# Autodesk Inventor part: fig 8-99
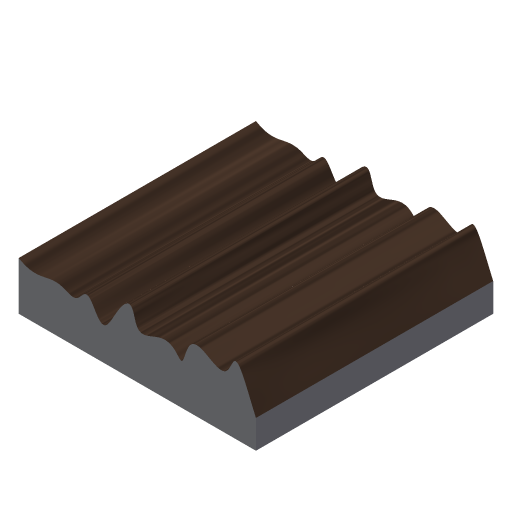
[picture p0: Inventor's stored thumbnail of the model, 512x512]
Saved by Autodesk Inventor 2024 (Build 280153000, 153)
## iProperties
Shininess: 64.0
Length Units: 11269
Angle Units: 11279
Time Units: 11290
Mass Units: 11283
Length Display Precision: 3
Angle Display Precision: 2
Compacted: True
Part Number: fig 8-99
Document SubType Name: Modeling
Created: 2002-12
Designer: deepak
Density: 1 g/cm^3
Material: Generic
Appearance: Default
Density: 0.0
Volumn: 0.0
Area: 0.0
PropertySet Name: Model Information
Control State: 0
Master: False
Checked Out: False
Author: deepak
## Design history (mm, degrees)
sketch "Sketch1"
  geometry: L1 (-32.188, 30.089)-(27.812, 30.089); L2 (27.812, 30.089)-(27.812, -29.911); L3 (27.812, -29.911)-(-32.188, -29.911); L4 (-32.188, -29.911)-(-32.188, 30.089)
  constraints: 8 end point, 2 parallel, 1 horizontal, 1 perpendicular
  dimensions: "d0" = 60 distance of L1.start L1.end; "d1" = 60 distance of L3.end L1.start
extrude "Extrusion1" new body sketch "Sketch1" stored distance "d2" = 20; taper "d3" = 0 deg
sketch "Sketch2"
  geometry: 17 further points
  constraints: 17 other
extrude_surface "ExtrusionSrf1" sketch "Sketch2" dims "d4" = 70, "d5" = 0
split "Split1"
body "Solid1"
body "Srf1"
